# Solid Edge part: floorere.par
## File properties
Author: Robert a Rhodes jr
Template: normal.par
Last saved by: Cadcim
Revision: 6
Application: Solid Edge
Accuracy: 0.99
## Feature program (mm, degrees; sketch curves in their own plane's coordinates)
sketch for "unnamed Protrusion 1" plane through (0, 0, 18.8714) normal (0, 0, 1) x-axis (1, 0, 0)
  line (-106.7153, 22.606) -> (-36.8209, 22.606)
  arc centre (-20.2938, 18.624) radius 17 from (-36.8209, 22.606) to (-36.6443, 13.97) cw
  line (-36.6443, 13.97) -> (-106.7153, 13.97)
  line (-106.7153, 13.97) -> (-106.7153, 22.606)
extrude "unnamed Protrusion 1" add finite 8.5604 along +normal
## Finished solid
Body 1: solid body, 6 faces, 12 edges, 8 vertices.
  Faces by surface: plane 5, cylinder 1
  Edges by curve: line 10, circle 2
Bounding box of the edges (mm): 103.421 x 34.000 x 8.560, from (-106.7153, 1.624, 18.8714) to (-3.2938, 35.624, 27.4319).
Cylindrical faces by radius (mm): R17 x1
Planar faces by outward normal: +y 1, +z 1, -x 1, -y 1, -z 1
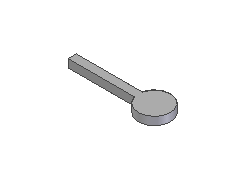
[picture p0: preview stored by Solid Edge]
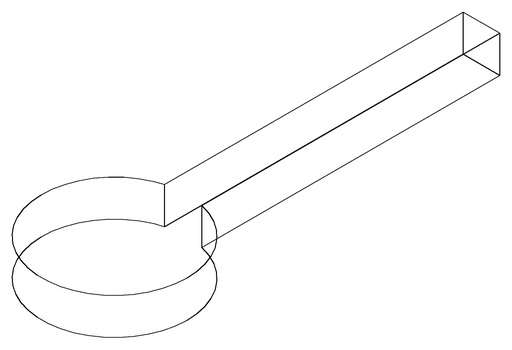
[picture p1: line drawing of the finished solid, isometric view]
